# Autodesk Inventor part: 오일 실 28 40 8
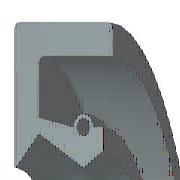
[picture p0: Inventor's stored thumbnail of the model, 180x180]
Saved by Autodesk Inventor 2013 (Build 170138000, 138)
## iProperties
IsCustomPart: 1
Created: 2012-02
Part Number: 오일 실 28 40 8
Material: 고무
Description: Oil-seal
Document SubType Name: Modeling
Standard: KS B 2804
Designer: mduedu
Standards Organization: KS
Language: en-US
Size Designation: D - 28 40 8
Categories: <MemberInstance><Categories><Category DisplayName="Shaft Parts" InternalName="7f7aeb1f-a693-4053-b835-cee3144e0d98" Mnemonic="SHFT"><Category DisplayName="Seali
Density: 0.93 g/cm^3
Mass: 2.83894 g
Surface Area: 40.7521 cm^2
Volume: 3.05262 cm^3
Author: mduedu
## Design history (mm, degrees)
sketch "Sketch1"
  geometry: L1 (0, 20)-(8, 20); L2 (8, 18.25)-(1.75, 18.25); L3 (1.75, 15.75)-(4.9, 14); L4 (4.9, 14)-(0, 14); L5 (0, 0)-(9.586, 0) reference; L6 (4.9, 14)-(6.3, 14.875); L7 (0, 18)-(0, -3) reference; L8 (-1.941, 0)-(11.507, 0) reference; L9 (4.2, 16.1)-(1.75, 16.71); L10 (1.75, 16.71)-(1.75, 18.25); L11 (0, 20)-(0, 14.088); L12 (4.9, 14)-(0, 14); L13 (1.75, 15.75)-(0.152, 14.028); L14 (8, 20)-(8, 18.25); L15 (5.6, 16.1)-(6.3, 16.1); L16 (6.3, 16.1)-(6.3, 14.875); C1 r 0.455 at (4.9, 16.1); A1 r 0.7 centre (4.9, 16.1) between (5.6, 16.1) and (4.2, 16.1); A2 r 0.088 centre (0.087, 14.088) between (0, 14.088) and (0.152, 14.028); 1 further point
  constraints: 28 end point, 5 horizontal alignment, 5 point on line, 4 point on circle, 4 vertical alignment, 3 centre point, 3 tangent, 2 collinear, 2 horizontal, 2 perpendicular, 1 coincident, 1 parallel
  dimensions: "d0" = 40 diameter of L1 L5 (= SD2); "d1" = 1.75 distance of L1.end L2.start (= SD); "d2" = 0.91 diameter of C1 (= SPDI); "d3" = 1.4 diameter of A1 (= SPDA); "d4" = 28 diameter of L3.end L5 (= NND); "d5" = 31.5 diameter of L3.start L5 (= TKDM); "d7" = 33.42 diameter of L9.end L5 (= TKDM + 0.24 x SWDT); "d8" = 1.75 distance between parallel lines of L11 L10 (= SD); "d9" = 4.9 distance from line of L11 C1.centre (= SPDST); "d10" = 32.2 diameter of C1.centre L5 (= HLDM); "d11" = 0.0875 radius of A2 (= 0.25 x LAB); "d12" = 6.3 distance between parallel lines of L11 L16 (= SDI); "d13" = 29.75 diameter of L6.end L5 (= ABDM); "d14" = 8 distance from line of L11 L1.end (= SWDT)
revolve "Body" stored, may be unused: angle "d17" = 90 deg
revolve "Spring1" stored, may be unused: angle "d18" = 90 deg
fillet "Fillet1" dims "d6" = 0.4 (= RR)
body "Solid1"
other parameters: "SD2" = 40 [user parameter; used in 1 equation term], "SWDT" = 8 [user parameter; used in 2 equation terms], "RR" = 0.4 [user parameter; used in 1 equation term], "SD" = 1.75 [user parameter; used in 2 equation terms], "NND" = 28 [user parameter; used in 1 equation term], "SPDA" = 1.4 [user parameter; used in 1 equation term], "SPDI" = 0.91 [user parameter; used in 1 equation term], "TKDM" = 31.5 [user parameter; used in 2 equation terms], "HLDM" = 32.2 [user parameter; used in 1 equation term], "ABDM" = 29.75 [user parameter; used in 1 equation term], "SDI" = 6.3 [user parameter; used in 1 equation term], "SPDST" = 4.9 [user parameter; used in 1 equation term], "LAB" = 0.35 [user parameter; used in 1 equation term], "d15" = 0, "d16" = 0, "d19" = 0
